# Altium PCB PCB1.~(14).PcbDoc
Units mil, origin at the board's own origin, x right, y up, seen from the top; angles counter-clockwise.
Board outline 3715 x 2925 mil, 2 copper layers (Top Layer, Bottom Layer); 4 components, 37 nets, 176 pads, 0 vias.
Unrouted connection lines stored in the file: 37.
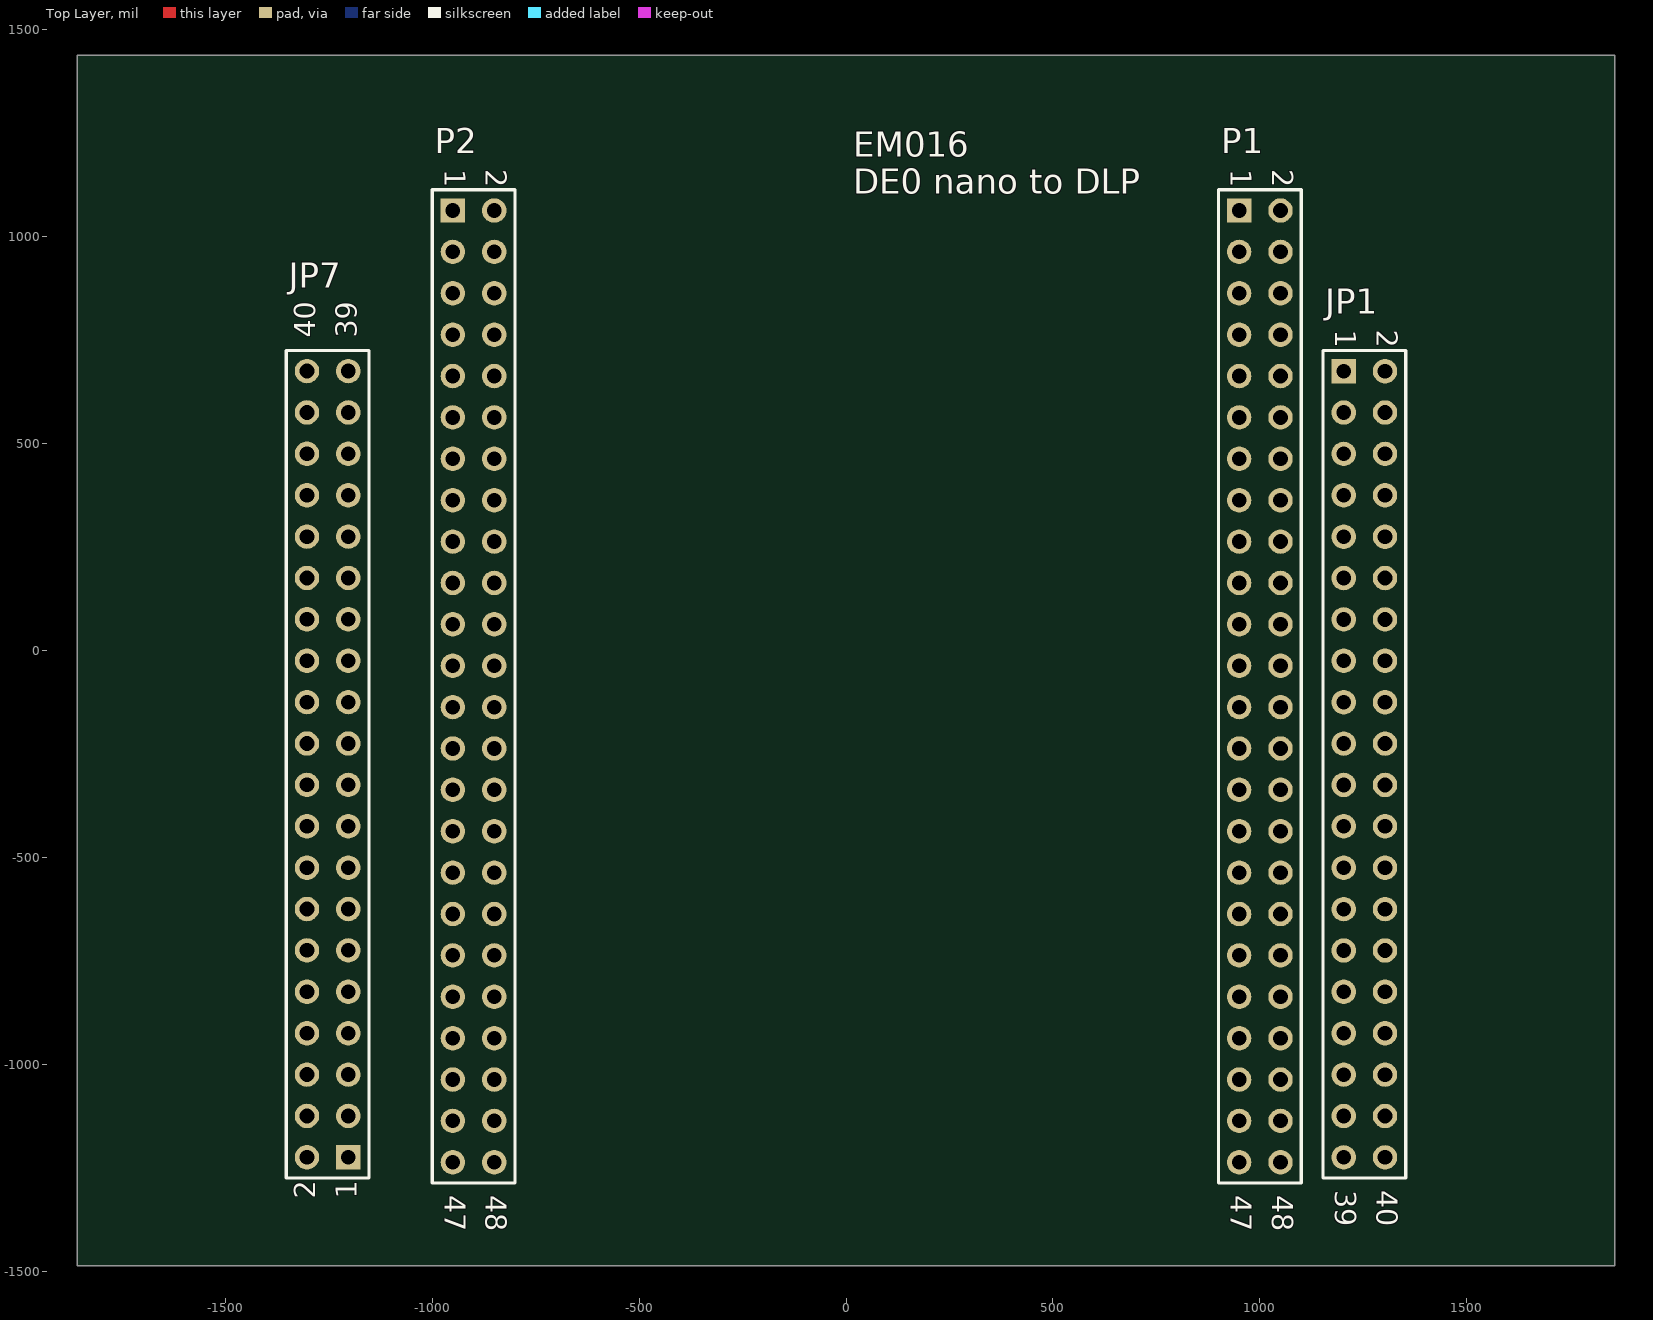
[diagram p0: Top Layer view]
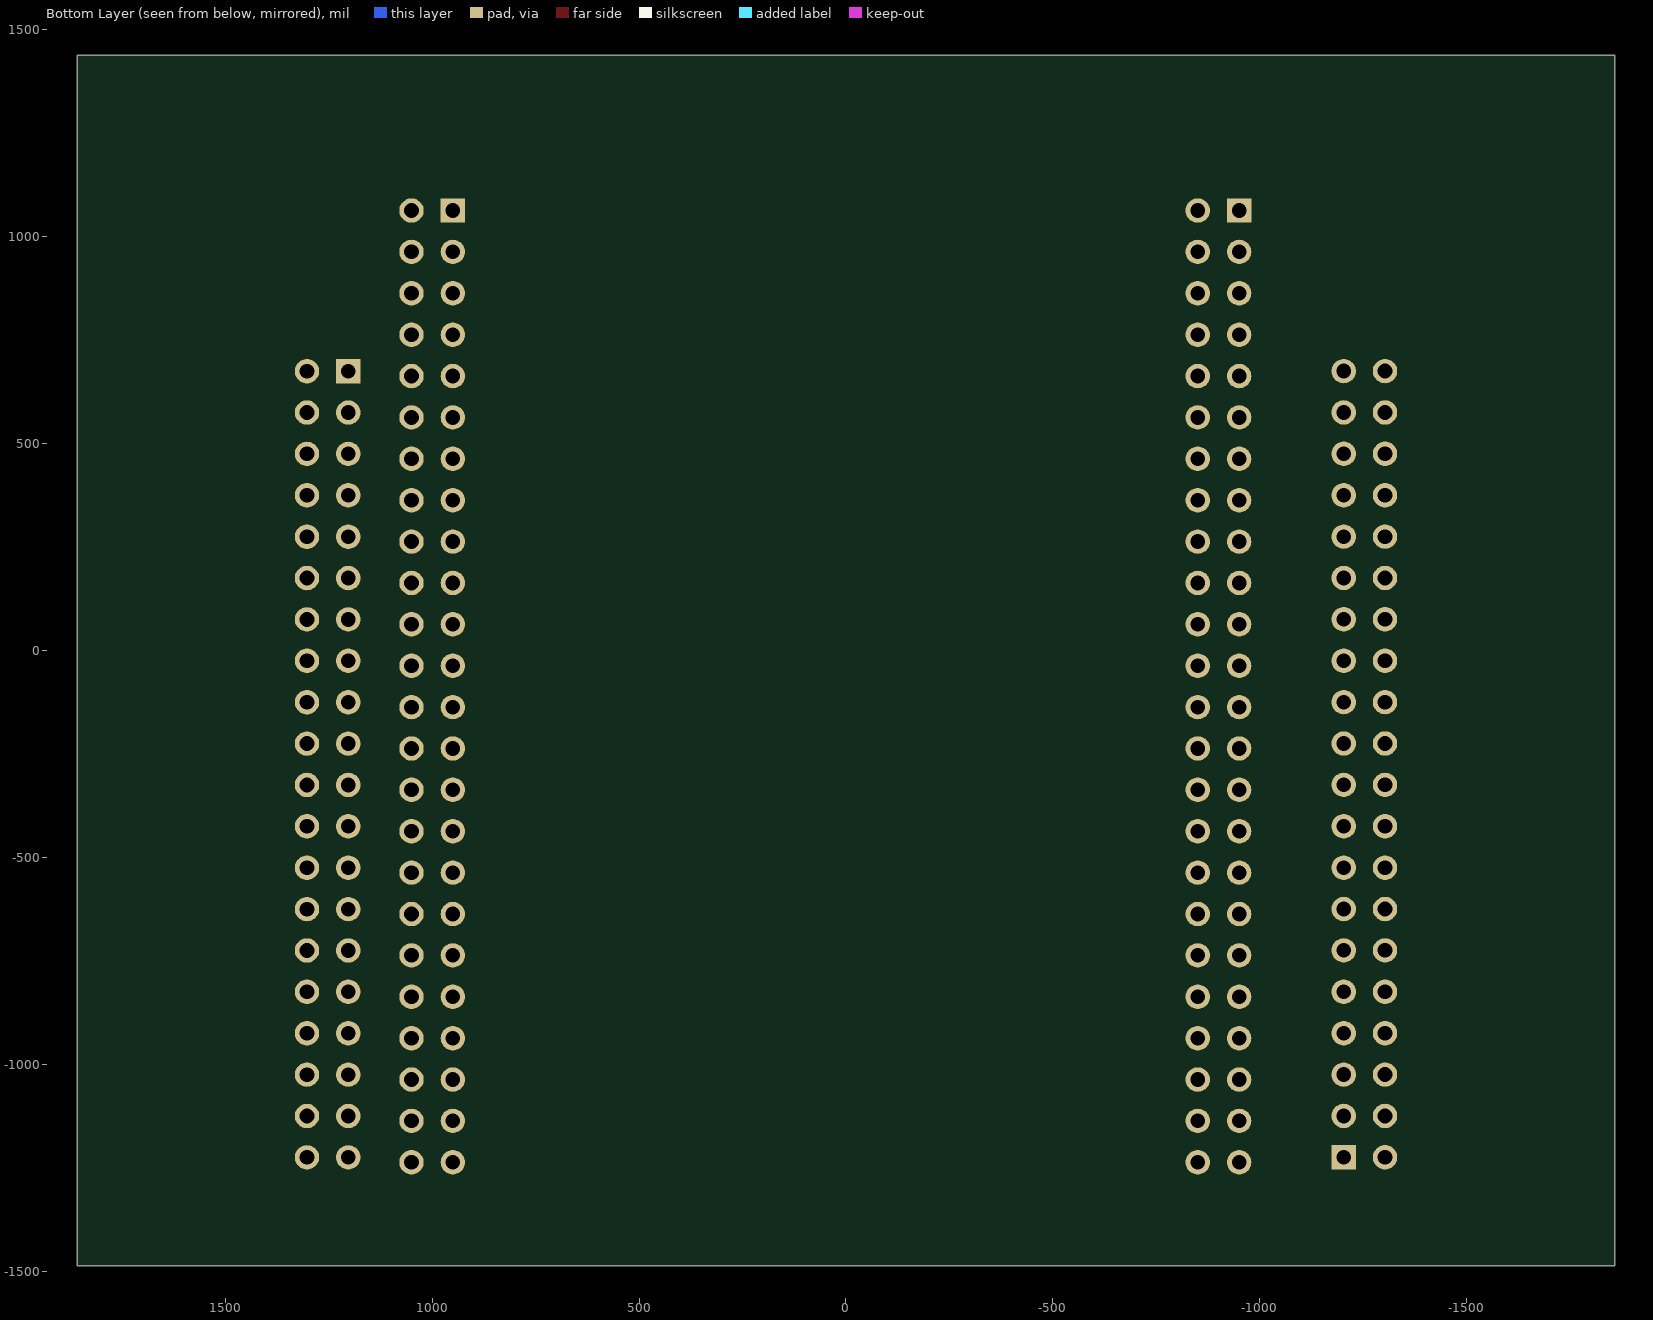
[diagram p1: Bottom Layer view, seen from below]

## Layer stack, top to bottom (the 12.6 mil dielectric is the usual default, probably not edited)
Top Solder: solder mask 0.4, Solder Resist, Dk 3.5
Top Layer: signal copper 1.4
Dielectric 1: dielectric 12.6, FR-4, Dk 4.8
Bottom Layer: signal copper 1.4
Bottom Solder: solder mask 0.4, Solder Resist, Dk 3.5

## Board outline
-1857.5,-1487.01 1857.5,-1487.01 1857.5,1437.99 -1857.5,1437.99

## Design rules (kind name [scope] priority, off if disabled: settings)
Clearance [All] p1: gap=10
PolygonConnect [All] p1: connectstyle=Relief reliefconductorwidth=10 reliefentries=4 polygonreliefangle="90 Angle" airgapwidth=10
RoomDefinition Sheet1 [InComponentClass('Sheet1')] p1 off: confinementstyle=ConfineIn formatcopy=TRUE lockcomponents=FALSE outline 4157.5,-2357.01 5522.5,-2357.01 5522.5,337.99 4157.5,337.99
RoutingVias [All] p1: holewidth=28 width=50 viastyle="Through Hole" minholewidth=28 minwidth=50 maxholewidth=28 maxwidth=50
SolderMaskExpansion [All] p1: expansion=4
Width [All] p1: maxlimit=10 minlimit=10 preferedwidth=10
30 further rules are at their usual default settings.

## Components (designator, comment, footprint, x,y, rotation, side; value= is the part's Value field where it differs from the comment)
JP1 "Header 20X2" HDR2X20 1202.56,674.84 r270 top
JP7 "Header 20X2" HDR2X20 -1202.56,-1225 r90 top
P1 "Header 24X2" HDR2X24 950,1062.99 r270 top
P2 "Header 24X2" HDR2X24 -950,1062.99 r270 top

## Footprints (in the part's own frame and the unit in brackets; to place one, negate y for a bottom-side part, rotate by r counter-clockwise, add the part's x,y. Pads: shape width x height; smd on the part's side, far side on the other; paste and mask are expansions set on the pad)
HDR2X20 [mm] "Connector; Header; 20x2 Position"
  rect 1.5x1.5 hole 0.9: 1(0,0)
  round 1.5 hole 0.9: 2(0,2.54) 3(2.54,0) 4(2.54,2.54) 5(5.08,0) 6(5.08,2.54) 7(7.62,0) 8(7.62,2.54) 9(10.16,0) 10(10.16,2.54) 11(12.7,0) 12(12.7,2.54) 13(15.24,0) 14(15.24,2.54) 15(17.78,0) 16(17.78,2.54) 17(20.32,0) 18(20.32,2.54) 19(22.86,0) 20(22.86,2.54) 21(25.4,0) 22(25.4,2.54) 23(27.94,0) 24(27.94,2.54) 25(30.48,0) 26(30.48,2.54) 27(33.02,0) 28(33.02,2.54) 29(35.56,0) 30(35.56,2.54) 31(38.1,0) 32(38.1,2.54) 33(40.64,0) 34(40.64,2.54) 35(43.18,0) 36(43.18,2.54) 37(45.72,0) 38(45.72,2.54) 39(48.26,0) 40(48.26,2.54)
  silkscreen extent -1.27,-1.27 49.53,3.81
HDR2X24 [mm] "Connector; Header; 24x2 Position"
  rect 1.5x1.5 hole 0.9: 1(0,0)
  round 1.5 hole 0.9: 2(0,2.54) 3(2.54,0) 4(2.54,2.54) 5(5.08,0) 6(5.08,2.54) 7(7.62,0) 8(7.62,2.54) 9(10.16,0) 10(10.16,2.54) 11(12.7,0) 12(12.7,2.54) 13(15.24,0) 14(15.24,2.54) 15(17.78,0) 16(17.78,2.54) 17(20.32,0) 18(20.32,2.54) 19(22.86,0) 20(22.86,2.54) 21(25.4,0) 22(25.4,2.54) 23(27.94,0) 24(27.94,2.54) 25(30.48,0) 26(30.48,2.54) 27(33.02,0) 28(33.02,2.54) 29(35.56,0) 30(35.56,2.54) 31(38.1,0) 32(38.1,2.54) 33(40.64,0) 34(40.64,2.54) 35(43.18,0) 36(43.18,2.54) 37(45.72,0) 38(45.72,2.54) 39(48.26,0) 40(48.26,2.54) 41(50.8,0) 42(50.8,2.54) 43(53.34,0) 44(53.34,2.54) 45(55.88,0) 46(55.88,2.54) 47(58.42,0) 48(58.42,2.54)
  silkscreen extent -1.27,-1.27 59.69,3.81

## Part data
JP1 JP7: "Header, 20-Pin, Dual row"
P1 P2: "Header, 24-Pin, Dual row"

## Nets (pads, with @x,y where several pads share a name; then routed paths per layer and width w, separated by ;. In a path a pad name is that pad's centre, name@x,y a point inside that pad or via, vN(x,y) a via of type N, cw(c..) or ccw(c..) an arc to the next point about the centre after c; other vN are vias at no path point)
3.3V: JP1.29 JP7.29 P2.3
DATA0: P1.45
DATA1: JP1.39 P1.46
DATA2: P1.43
DATA3: JP1.37 P1.44
DATA4: P1.41
DATA5: JP1.35 P1.42
DATA6: P1.39
DATA7: JP1.33 P1.40
DATA8: P1.37
DATA9: JP1.31 P1.38
DATA10: JP1.27 P1.36
DATA11: JP1.25 P1.34
DATA12: JP1.28 P1.35
DATA13: JP1.26 P1.33
DATA14: JP1.24 P1.31
DATA15: JP1.23 P1.32
DATA16: JP1.10 P1.15
DATA17: JP1.9 P1.16
DATA18: JP1.6 P1.11
DATA19: JP1.5 P1.12
DATA20: JP1.14 P1.17
DATA21: JP1.7 P1.14
DATA22: JP1.8 P1.13
DATA23: JP1.16 P1.19
DATAEN: JP1.21 P1.30
EXT_SCL: JP7.21 P2.19
EXT_SDA: JP7.22 P2.20
GND: JP7.12 JP7.30 P2.1 P2.44 P2.45 P2.46
GPIO5: JP1.13 P1.18
GPIO_INIT_DONE: JP1.17 P1.26
HOST_PRESENT: JP7.3 P2.43
HSYNC: JP1.22 P1.29
PCLK: JP1.19 P1.28
PROJ_ON_EXT: JP7.25 P2.15
VCC5: JP1.11 JP7.11
VSYNC: JP1.20 P1.27
pads on no net: JP1.1 JP1.2 JP1.3 JP1.4 JP1.12 JP1.15 JP1.18 JP1.30 JP1.32 JP1.34 JP1.36 JP1.38 JP1.40 JP7.1 JP7.2 JP7.4 JP7.5 JP7.6 JP7.7 JP7.8 JP7.9 JP7.10 JP7.13 JP7.14 JP7.15 JP7.16 JP7.17 JP7.18 JP7.19 JP7.20 JP7.23 JP7.24 JP7.26 JP7.27 JP7.28 JP7.31 JP7.32 JP7.33 JP7.34 JP7.35 JP7.36 JP7.37 JP7.38 JP7.39 JP7.40 P1.1 P1.2 P1.3 P1.4 P1.5 P1.6 P1.7 P1.8 P1.9 P1.10 P1.20 P1.21 P1.22 P1.23 P1.24 P1.25 P1.47 P1.48 P2.2 P2.4 P2.5 P2.6 P2.7 P2.8 P2.9 P2.10 P2.11 P2.12 P2.13 P2.14 P2.16 P2.17 P2.18 P2.21 P2.22 P2.23 P2.24 P2.25 P2.26 P2.27 P2.28 P2.29 P2.30 P2.31 P2.32 P2.33 P2.34 P2.35 P2.36 P2.37 P2.38 P2.39 P2.40 P2.41 P2.42 P2.47 P2.48

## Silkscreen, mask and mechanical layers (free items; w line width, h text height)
Top Overlay:
  text "EM016 / DE0 nano to DLP" at 17.5,1102.99 h60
